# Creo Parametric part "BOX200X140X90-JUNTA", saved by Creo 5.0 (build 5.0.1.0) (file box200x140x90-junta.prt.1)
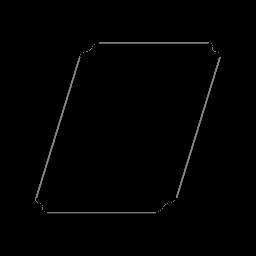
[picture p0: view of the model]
Units: millimeter Kilogram Sec (mmKs); MM, KILOGRAM, SECS
Materials in the file: NBR

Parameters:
  PTC_MATERIAL_NAME = "NBR"
  USO = "Estático a la intemperie"

Other parameters: SHORE_A, TEMPERATURA_MAX, TEMPERATURA_MIN

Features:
  1. coordinate system "BOX200X140X90-JUNTA"
  2. imported feature "Función De Importación ID 5"
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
